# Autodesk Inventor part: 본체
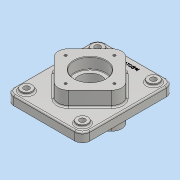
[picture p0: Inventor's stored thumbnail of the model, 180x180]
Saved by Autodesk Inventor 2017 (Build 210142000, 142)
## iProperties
Part Number: 본체
Material: 알루미늄 6061
Document SubType Name: Modeling
Designer: MRC
Density: 2.7 g/cm^3
Appearance: 알루미늄 - 평지
Mass: 2181.54 g
Surface Area: 961.758 cm^2
Volume: 807.977 cm^3
Author: MRC
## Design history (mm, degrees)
sketch "스케치1"
  geometry: L1 (-75, 90)-(75, 90); L2 (75, 90)-(75, -90); L3 (75, -90)-(-75, -90); L4 (-75, -90)-(-75, 90); L5 (-75, 90)-(75, -90); L6 (75, 90)-(-75, -90); 1 further point
  constraints: 12 end point, 2 midpoint, 2 parallel, 1 horizontal, 1 perpendicular
  dimensions: "d0" = 150 distance of L2.end L3.end; "d1" = 180 distance of L1.end L2.end
extrude "돌출1" new body sketch "스케치1" stored distance "d2" = 18; taper "d3" = 0 deg
sketch "스케치2"
  geometry: L1 (0, 70.711)-(70.711, 0); L2 (70.711, 0)-(0, -70.711); L3 (0, -70.711)-(-70.711, 0); L4 (-70.711, 0)-(0, 70.711); 2 further points
  constraints: 8 end point, 1 coincident, 1 horizontal alignment, 1 vertical alignment, 9 other
  dimensions: "d4" = 100 distance of L1.start L1.end
extrude "돌출2" join sketch "스케치2" distance "d5" = 29; taper "d7" = 0 deg; dims "d6" = 41, "d8" = 0
sketch "스케치3"
  geometry: 2 further points
  constraints: 1 coincident
hole "구멍1" sketch "스케치3" at (0, 0) diameter "d9" = 45; stored, may be unused: countersink angle "d13" = 90 deg, drill point angle "d15" = 118 deg; dims "d10" = 6, "d11" = 62, "d12" = 22, "d14" = 8
sketch "스케치4"
  geometry: C1 r 31 at (0, 0); 1 further point
  constraints: 1 centre point, 1 coincident
  dimensions: "d16" = 62 diameter of C1
extrude "돌출3" cut sketch "스케치4" distance "d17" = 22; taper "d18" = 0 deg
fillet "모깎기1" dims "d19" = 20
sketch "스케치5"
  geometry: 2 further points
  constraints: 1 vertical alignment
  dimensions: "d21" = 48 distance of point (0, 0) point (0, 48)
hole "구멍2" sketch "스케치5" at (0, 48) diameter "d22" = 4.917; stored, may be unused: countersink angle "d26" = 90 deg, drill point angle "d28" = 118 deg; dims "d23" = 10, "d24" = 62, "d25" = 22, "d27" = 13
sketch "스케치6"
  geometry: 2 further points
  constraints: 1 vertical alignment
  dimensions: "d32" = 48 distance of point (0, 0) point (0, 48)
hole "구멍3" sketch "스케치6" at (0, 48) diameter "d33" = 4.917; stored, may be unused: countersink angle "d37" = 90 deg, drill point angle "d39" = 118 deg; dims "d34" = 10, "d35" = 62, "d36" = 22, "d38" = 13
fillet "모깎기2" dims "d43" = 15
fillet "모깎기3" dims "d44" = 3
fillet "모깎기4" dims "d45" = 1
fillet "모깎기5" dims "d46" = 1
chamfer "모따기1" distance "d47" = 1; stored, may be unused: second distance "d48" = 2, angle "d49" = 45 deg
chamfer "모따기2" distance "d50" = 1; stored, may be unused: second distance "d51" = 2, angle "d52" = 45 deg
sketch "스케치9"
  geometry: L1 (-75, 75)-(-75, -75) reference; L2 (60, 90)-(-60, 90) reference; C1 r 11 at (-55, 70); 1 further point
  constraints: 1 centre point
  dimensions: "d57" = 22 diameter of C1; "d63" = 20 distance from line of C1.centre L1; "d65" = 20 distance from line of L2 C1.centre
extrude "돌출4" join sketch "스케치9" distance "d66" = 5; taper "d67" = 0 deg
sketch "스케치10"
  geometry: C1 r 5.5 at (0, 0); 1 further point
  constraints: 1 centre point
  dimensions: "d68" = 11 diameter of C1
extrude "돌출5" cut sketch "스케치10" stored distance "d69" = 5; taper "d70" = 0 deg
fillet "모깎기6" dims "d71" = 3
sketch "스케치12"
  geometry: L1 (60, 90)-(-60, 90) reference; 2 further points
  constraints: 1 vertical alignment, 1 other
  dimensions: "d72" = 15 distance from line of L1 point (0, 75)
feature "엠보싱1" sketch "스케치12" dims "d0" = 150, "d1" = 180, "d73" = 0.5, "d74" = 0
node "솔리드1"
pattern_circular "원형 패턴1" dims angle "d30" = 360 deg
pattern_circular "원형 패턴2" dims angle "d41" = 360 deg
mirror "미러1"
mirror "미러2"
